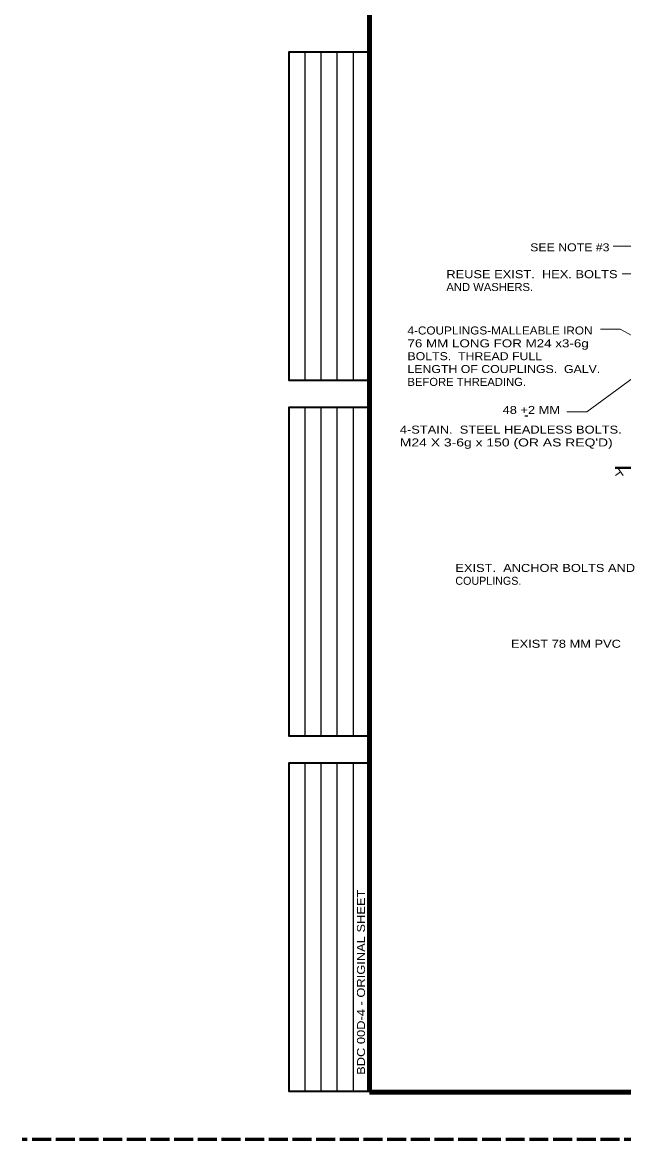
# Model space of a CAD drawing. Extents: x 312583 to 312853, y 144419 to 144586.
# Drawn here: x 312583.5 to 312640.7, y 144418.6 to 144524.7 of the extents above; entities that cross this region are included whole.
import ezdxf

# ---------------------------------------------------------------- set-up
doc = ezdxf.new("R2010")
doc.units = 0
doc.header["$LTSCALE"] = 0.3
doc.linetypes.add('LONG_DASHED', pattern=[7.5, 6, -1.5])
doc.layers.add('1', color=7, linetype='Continuous', lineweight=40)
doc.layers.add('2', color=7, linetype='Continuous', lineweight=13)

msp = doc.modelspace()

# ---------------------------------------------------------------- linework, layer by layer
at = {"layer": '1', "lineweight": 25}
for p, q in [((312610.4087, 144490.6573), (312610.4087, 144521.8756)), ((312611.9315, 144490.6573), (312611.9315, 144521.8756)), ((312613.4543, 144490.6573), (312613.4543, 144521.8756)), ((312614.9772, 144490.6573), (312614.9772, 144521.8756)), ((312610.4087, 144456.901), (312610.4087, 144488.1192)), ((312611.9315, 144456.901), (312611.9315, 144488.1192)), ((312613.4543, 144456.901), (312613.4543, 144488.1192)), ((312614.9772, 144456.901), (312614.9772, 144488.1192)), ((312610.4087, 144423.1446), (312610.4087, 144454.3629)), ((312611.9315, 144423.1446), (312611.9315, 144454.3629)), ((312613.4543, 144423.1446), (312613.4543, 144454.3629)), ((312614.9772, 144423.1446), (312614.9772, 144454.3629))]:
    msp.add_line(p, q, dxfattribs=at)
at = {"layer": '1'}
msp.add_line((312639.8655, 144482.3729), (312644.3122, 144482.3729), dxfattribs=at)
at = {"layer": '1', "lineweight": 158}
msp.add_line((312616.5, 144423.0846), (312849, 144423.0846), dxfattribs=at)
at = {"layer": '1', "linetype": 'LONG_DASHED', "lineweight": 60}
msp.add_line((312851.75, 144418.5846), (312583.526, 144418.5846), dxfattribs=at)
msp.add_line((312851.75, 144418.5846), (312583.526, 144418.5846), dxfattribs=at)
at = {"layer": '1', "lineweight": 158}
msp.add_lwpolyline([(312616.5, 144423.1446), (312616.5, 144585.0846), (312849, 144585.0846)], dxfattribs=at)
at = {"layer": '1', "lineweight": 35}
for points in [[(312616.5, 144490.6573), (312608.8858, 144490.6573), (312608.8858, 144521.8756), (312616.5, 144521.8756)], [(312616.5, 144456.901), (312608.8858, 144456.901), (312608.8858, 144488.1192), (312616.5, 144488.1192)], [(312616.5, 144423.1446), (312608.8858, 144423.1446), (312608.8858, 144454.3629), (312616.5, 144454.3629)]]:
    msp.add_lwpolyline(points, dxfattribs=at)
at = {"layer": '2'}
for p, q in [((312639.6739, 144503.4026), (312643.3539, 144503.4026)), ((312642.8479, 144500.7806), (312640.5259, 144500.7806)), ((312637.1745, 144487.6783), (312643.2925, 144492.1786)), ((312635.2732, 144487.6783), (312637.1745, 144487.6783)), ((312639.8809, 144481.6369), (312640.3715, 144481.9819)), ((312640.0725, 144482.4036), (312640.6169, 144481.6369))]:
    msp.add_line(p, q, dxfattribs=at)
msp.add_lwpolyline([(312648.0459, 144491.3199), (312640.3255, 144495.5289), (312638.4702, 144495.5289)], dxfattribs=at)

# ---------------------------------------------------------------- texts
at = {"layer": '1', "width": 1.2}
msp.add_text('BDC 00D-4 - ORIGINAL SHEET', height=0.7614, rotation=90, dxfattribs=at).set_placement((312616.0832, 144424.7374))
at = {"layer": '2'}
for s, width, p in [('SEE NOTE #3', 1.15, (312631.7762, 144502.9232)), ('REUSE EXIST.  HEX. BOLTS', 1.2, (312623.8117, 144500.3733)), ('AND WASHERS.', 1.05, (312623.8117, 144499.1533)), ('4-COUPLINGS-MALLEABLE IRON', 1.1, (312620.1167, 144495.0261)), ('76 MM LONG FOR M24 x3-6g', 1.25, (312620.1167, 144493.8061)), ('BOLTS.  THREAD FULL', 1.15, (312620.1167, 144492.5861)), ('LENGTH OF COUPLINGS.  GALV.', 1.15, (312620.1167, 144491.3661)), ('BEFORE THREADING.', 1.05, (312620.1167, 144490.1461)), ('48 +2 MM', 1.2, (312629.1589, 144487.4825)), ('4-STAIN.  STEEL HEADLESS BOLTS.', 1.2, (312619.3941, 144485.6161)), ("M24 X 3-6g x 150 (OR AS REQ'D)", 1.3, (312619.3941, 144484.3961)), ('EXIST.  ANCHOR BOLTS AND ', 1.2, (312624.6681, 144472.4831)), ('EXIST 78 MM PVC', 1.2, (312629.957, 144465.2818))]:
    msp.add_text(s, height=0.76, dxfattribs=dict(at, width=width)).set_placement(p)
for s, height, p in [('-', 0.92, (312631.211, 144486.9337)), ('COUPLINGS.', 0.76, (312624.6681, 144471.2631))]:
    msp.add_text(s, height=height, dxfattribs=at).set_placement(p)

doc.saveas('drawing.dxf')
